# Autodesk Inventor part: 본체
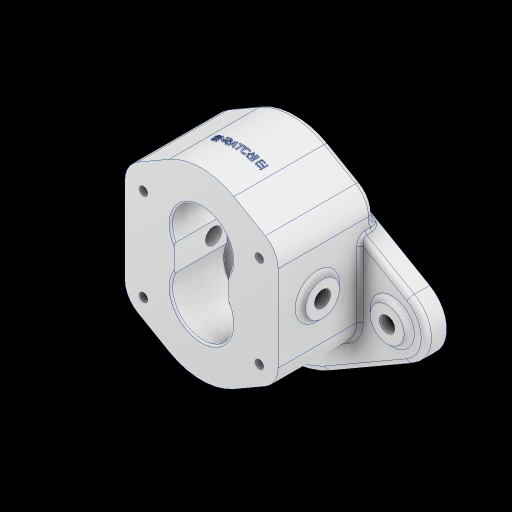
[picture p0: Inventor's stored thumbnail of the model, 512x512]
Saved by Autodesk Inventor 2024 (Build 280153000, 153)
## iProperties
Created: 2025-11
Part Number: 본체
Material: 알루미늄 6061
Document SubType Name: Modeling
Designer: EDU03
Density: 2.7 g/cm^3
Appearance: 알루미늄 - 평지
Mass: 1254.17 g
Surface Area: 588.445 cm^2
Volume: 464.508 cm^3
Author: EDU03
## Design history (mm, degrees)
sketch "스케치1" dims "d0" = 104, "d2" = 40
  geometry: L1 (0, 0)-(0, 84.803); L2 (-74, 17.321)-(-26, 45.033); L3 (74, 17.321)-(26, 45.033); L4 (0, 0)-(28.765, 0); L5 (74, -17.321)-(26, -45.033); L6 (-74, -17.321)-(-26, -45.033); C1 r 20 at (64, 0); 8 further points
  constraints: 12 end point, 7 symmetric about line, 1 centre point, 1 coincident, 1 horizontal, 1 horizontal alignment, 1 vertical, 9 other
  dimensions: "d1" = 128 diameter of point (-64, 0) L1
extrude "돌출1" new body sketch "스케치1" distance "d3" = 12; taper "d4" = 0 deg
sketch "스케치2"
  geometry: L1 (-26, 45.033)-(-74, 17.321) reference; L2 (-74, -17.321)-(-26, -45.033) reference; L3 (26, -45.033)-(74, -17.321) reference; L4 (74, 17.321)-(26, 45.033) reference; C1 r 10 at (-64, 0); C2 r 10 at (64, 0); A1 r 20 centre (-64, 0) between (-74, 17.321) and (-74, -17.321) reference; A2 r 52 centre (0, 0) between (-26, -45.033) and (26, -45.033) reference; A3 r 20 centre (64, 0) between (74, -17.321) and (74, 17.321) reference; A4 r 52 centre (0, 0) between (26, 45.033) and (-26, 45.033) reference; 1 further point
  constraints: 2 centre point, 2 coincident
  dimensions: "d5" = 20 diameter of C1; "d6" = 20 diameter of C2
extrude "돌출2" join sketch "스케치2" distance "d7" = 3; taper "d8" = 0 deg
sketch "스케치3"
  geometry: C1 r 10 at (0, 0) reference; C2 r 10 at (128, 0) reference; 3 further points
  constraints: 2 coincident
hole "구멍1" sketch "스케치3" at (0, 0), (128, 0) diameter "d9" = 9; stored, may be unused: countersink angle "d13" = 90 deg, drill point angle "d15" = 118 deg; dims "d10" = 6, "d11" = 4, "d12" = 2, "d14" = 8
sketch "스케치4"
  geometry: C1 r 25 at (0, 0); 1 further point
  constraints: 1 centre point, 1 coincident
  dimensions: "d16" = 50 diameter of C1
extrude "돌출3" join sketch "스케치4" distance "d17" = 4; taper "d18" = 0 deg
fillet "모깎기1" dims "d19" = 3
chamfer "모따기1" distance "d20" = 1; stored, may be unused: second distance "d21" = 2, angle "d22" = 45 deg
sketch "스케치5"
  geometry: L1 (0, 0)-(0, 16); L2 (0, 16)-(0, 32); L3 (-34, 98.421)-(-34, -70.713); L4 (0, 0)-(15.008, 0); L5 (-60.9, 43)-(46.18, 43); L6 (0, 16)-(11.834, 16); L7 (14.497, 67.509)-(45, 49.898); L8 (34, 43)-(34, -11); L9 (-45, -22.719)-(-45, 54.719); L10 (45, -22.719)-(45, 49.898); L11 (14.497, -35.509)-(45, -17.898); L12 (-14.497, 67.509)-(-45, 49.898); L13 (-14.497, -35.509)-(-45, -17.898); C1 r 38 at (0, 32); C2 r 38 at (0, 0); C3 r 2.163 at (-38.837, -22.891); 4 further points
  constraints: 26 end point, 10 symmetric about line, 4 vertical, 3 centre point, 3 horizontal, 2 coincident, 2 parallel, 1 point on line, 1 tangent
  dimensions: "d23" = 16 distance of L1.start L1.end; "d24" = 16 distance of L1.end L2.end; "d25" = 76 diameter of C1; "d26" = 76 diameter of C2; "d27" = 34 distance from line of L1.start L3; "d34" = 54 distance of L8.end L8.start; "d68" = 45 distance between parallel lines of L1 L9; "d69" = 45 distance between parallel lines of L1 L10; "d70" = 30 deg angle of L6 L7
node "작업 평면1"
sketch "스케치6"
  geometry: L1 (-14.497, 67.509)-(-45, 49.898) reference; L2 (-45, -22.719)-(-45, 49.898) reference; L3 (-14.497, -35.509)-(-45, -17.898) reference; L4 (14.497, -35.509)-(45, -17.898) reference; L5 (45, -22.719)-(45, 54.719) reference; L6 (14.497, 67.509)-(45, 49.898) reference; C1 r 38 at (0, 32) reference; C2 r 38 at (0, 0) reference
node "작업 평면3"
node "작업 평면4"
sketch "스케치8"
  geometry: L1 (-39.652, 56.895)-(-14.318, 67.199) reference; L2 (39.652, -24.895)-(14.318, -35.199) reference; L3 (0, 0)-(0, 32); L4 (-16, 0)-(-16, 32); L5 (16, 0)-(16, 32); C1 r 18 at (0, 32); C2 r 18 at (0, 0); A1 r 2.458 centre (34, -11) between (36.446, -10.755) and (35.839, -12.631) reference; A2 r 2.458 centre (34, 43) between (35.839, 44.631) and (36.446, 42.755) reference; A3 r 2.458 centre (-34, 43) between (-36.446, 42.755) and (-35.839, 44.631) reference; A4 r 15 centre (34, 43) between (28.617, 57.001) and (37.838, 28.499) reference; A5 r 38 centre (0, 32) between (-14.318, 67.199) and (-28.617, 57.001) reference; A6 r 15 centre (-34, 43) between (-28.617, 57.001) and (-39.652, 56.895) reference; A7 r 38 centre (0, 0) between (36.446, -10.755) and (37.838, 3.501) reference; A8 r 15 centre (34, -11) between (37.838, 3.501) and (28.617, -25.001) reference; A9 r 38 centre (0, 32) between (-34.467, 16) and (34.467, 16) reference; A10 r 38 centre (0, 0) between (34.467, 16) and (-34.467, 16) reference; A11 r 15 centre (34, -11) between (28.617, -25.001) and (39.652, -24.895) reference; A12 r 38 centre (0, 0) between (14.318, -35.199) and (28.617, -25.001) reference; A13 r 38 centre (0, 32) between (-36.446, 42.755) and (-37.838, 28.499) reference; A14 r 15 centre (-34, 43) between (-37.838, 28.499) and (-28.617, 57.001) reference; A15 r 38 centre (0, 32) between (-28.617, 57.001) and (-35.839, 44.631) reference; A16 r 38 centre (0, 32) between (35.839, 44.631) and (28.617, 57.001) reference; A17 r 38 centre (0, 32) between (37.838, 28.499) and (36.446, 42.755) reference; A18 r 38 centre (0, 0) between (28.617, -25.001) and (35.839, -12.631) reference; 5 further points
  constraints: 6 end point, 2 centre point, 2 coincident, 2 parallel, 1 vertical
  dimensions: "d42" = 36 diameter of C1; "d43" = 36 diameter of C2; "d44" = 16 distance between parallel lines of L3 L4; "d45" = 16 distance between parallel lines of L3 L5
extrude "돌출5" cut sketch "스케치8" distance "d46" = 31; taper "d47" = 0 deg
node "작업 평면8"
sketch "스케치10"
  geometry: L1 (16, 23.754)-(16, 8.246) reference; L2 (-16, 8.246)-(-16, 23.754) reference; C1 r 11.5 at (0, 32); C2 r 11.5 at (0, 0); A1 r 18 centre (0, 0) between (17.937, -1.5) and (16, 8.246) reference; A2 r 18 centre (0, 32) between (-17.937, 33.5) and (-16, 23.754) reference; A3 r 38 centre (0, 0) between (17.937, 33.5) and (-17.937, 33.5) reference; A4 r 18 centre (0, 0) between (-16, 8.246) and (-17.937, -1.5) reference; A5 r 38 centre (0, 32) between (-17.937, -1.5) and (17.937, -1.5) reference; A6 r 18 centre (0, 32) between (16, 23.754) and (17.937, 33.5) reference; 1 further point
  constraints: 2 centre point, 2 coincident
  dimensions: "d48" = 23 diameter of C1; "d49" = 23 diameter of C2
extrude "돌출6" cut sketch "스케치10" distance "d50" = 46; taper "d51" = 0 deg
sketch "스케치12"
  geometry: C1 r 15 at (0, 0); 1 further point
  constraints: 1 centre point, 1 coincident
  dimensions: "d55" = 30 diameter of C1
extrude "돌출8" cut sketch "스케치12" distance "d56" = 7.3; taper "d57" = 0 deg
fillet "모깎기3" dims "d61" = 0.3
chamfer "모따기3" distance "d62" = 0.35; stored, may be unused: second distance "d63" = 0.7, angle "d64" = 45 deg
node "작업 평면7"
sketch "스케치14"
  geometry: L1 (-14.497, 67.509)-(-45, 49.898) reference; L2 (-45, -22.719)-(-45, 54.719) reference; L3 (-14.497, -35.509)-(-45, -17.898) reference; L4 (14.497, -35.509)-(45, -17.898) reference; L5 (45, -22.719)-(45, 49.898) reference; L6 (14.497, 67.509)-(45, 49.898) reference; C1 r 38 at (0, 32) reference; C2 r 38 at (0, 0) reference; 5 further points
extrude "돌출9" join sketch "스케치14" distance "d71" = 56; taper "d72" = 0 deg
sketch "스케치15"
  geometry: L1 (45, -17.898)-(45, 49.898) reference; L2 (45, 49.898)-(19, 64.909) reference; L3 (-19, 64.909)-(-45, 49.898) reference; L4 (-45, 49.898)-(-45, -17.898) reference; L5 (-45, -17.898)-(-19, -32.909) reference; L6 (19, -32.909)-(45, -17.898) reference; A1 r 38 centre (0, 32) between (19, 64.909) and (-19, 64.909) reference; A2 r 38 centre (0, 0) between (-19, -32.909) and (19, -32.909) reference; 5 further points
  constraints: 2 vertical alignment
  dimensions: "d119" = 68 distance of point (-34, 41.238) point (34, 41.238); "d120" = 34 horizontal distance of A1.centre point (34, 41.238); "d121" = 54 distance of point (34, -12.762) point (34, 41.238); "d122" = 54 distance of point (-34, 41.238) point (-34, -12.762)
hole "구멍3" sketch "스케치15" at (-34, -12.762), (-34, 41.238), (34, 41.238), (34, -12.762) diameter "d74" = 4.917; stored, may be unused: countersink angle "d78" = 90 deg, drill point angle "d80" = 118 deg; dims "d75" = 12, "d76" = 4, "d77" = 2, "d79" = 14
node "작업 평면9"
sketch "스케치16"
  geometry: L1 (0, 0)-(0, 32); L2 (16, 0)-(16, 32); L3 (-16, 0)-(-16, 32); C1 r 18 at (0, 0); C2 r 18 at (0, 32); 5 further points
  constraints: 6 end point, 2 centre point, 2 coincident, 2 parallel, 1 vertical
  dimensions: "d81" = 36 diameter of C1; "d82" = 32 distance of L1.start L1.end; "d83" = 36 diameter of C2; "d84" = 16 distance between parallel lines of L1 L2; "d85" = 16 distance between parallel lines of L1 L3
extrude "돌출10" cut sketch "스케치16" distance "d86" = 31; taper "d87" = 0 deg
node "작업 평면10"
sketch "스케치17"
  geometry: L1 (-16, 8.246)-(-16, 23.754) reference; L2 (16, 23.754)-(16, 8.246) reference; L3 (45, -17.898)-(45, 49.898) reference; L4 (45, 49.898)-(19, 64.909) reference; L5 (-19, 64.909)-(-45, 49.898) reference; L6 (-45, 49.898)-(-45, -17.898) reference; L7 (-45, -17.898)-(-19, -32.909) reference; L8 (19, -32.909)-(45, -17.898) reference; C1 r 11.5 at (0, 0); C2 r 2.458 at (-34, -12.762) reference; C3 r 11.5 at (0, 32); A1 r 18 centre (0, 32) between (16, 23.754) and (-16, 23.754) reference; A2 r 18 centre (0, 0) between (-16, 8.246) and (16, 8.246) reference; A3 r 38 centre (0, 32) between (19, 64.909) and (-19, 64.909) reference; A4 r 38 centre (0, 0) between (-19, -32.909) and (19, -32.909) reference; 1 further point
  constraints: 2 centre point, 1 coincident
  dimensions: "d88" = 23 diameter of C1; "d89" = 23 diameter of C3
extrude "돌출11" cut sketch "스케치17" distance "d90" = 24; taper "d91" = 0 deg
node "작업 평면11"
sketch "스케치18"
  geometry: C1 r 10.5 at (0, 0); 1 further point
  constraints: 1 centre point, 1 coincident
  dimensions: "d92" = 21 diameter of C1
extrude "돌출12" cut sketch "스케치18" extent not by distance; stored distance "d93" = 0; taper "d94" = 0 deg
fillet "모깎기5" dims "d97" = 15
node "작업 평면12"
sketch "스케치21"
  geometry: L1 (-51, -10.31)-(-51, -25.817) reference; L2 (-51, -18.064)-(-28, -18.064); C1 r 10 at (-28, -18.064); 1 further point
  constraints: 2 end point, 1 centre point, 1 coincident, 1 horizontal, 1 midpoint
  dimensions: "d99" = 23 distance of L2.start L2.end; "d100" = 20 diameter of C1
extrude "돌출13" join sketch "스케치21" stored distance "d101" = 10; taper "d102" = 0 deg
sketch "스케치22"
  geometry: L1 (-23, -25.238)-(-23, 25.238) reference; C1 r 10 at (0, 0) reference; 2 further points
  constraints: 1 coincident
  dimensions: "d114" = 23 distance from line of point (0, 0) L1 (derived)
hole "구멍4" sketch "스케치22" at (0, 0) diameter "d103" = 9.3762; stored, may be unused: countersink angle "d107" = 90 deg, drill point angle "d109" = 118 deg; dims "d104" = 22, "d105" = 4, "d106" = 2, "d108" = 14
feature "스레드1" dims "d110" = 5, "d111" = 0
fillet "모깎기6" dims "d112" = 3
fillet "모깎기7" dims "d113" = 1
node "작업축1"
node "작업 평면14"
sketch "스케치23"
  geometry: 2 further points
  constraints: 1 other
feature "엠보싱1" sketch "스케치23" dims "d115" = 0.5, "d116" = 0
fillet "모깎기8" dims "d117" = 3
fillet "모깎기9" dims "d118" = 2
node "솔리드1"
mirror "미러1"
node "투영된 루프1"
node "투영된 루프3"
node "투영된 루프4"
node "투영된 루프5"
node "투영된 루프6"
feature "A9D066F2-1C7D-4E18-AEED-F7BC21143FA4" dims "d74" = 4.917, "d75" = 12, "d76" = 4, "d77" = 2, "d78" = 90 deg, "d79" = 14, "d80" = 118 deg
other parameters: "d30" = -64, "d98" = 3
